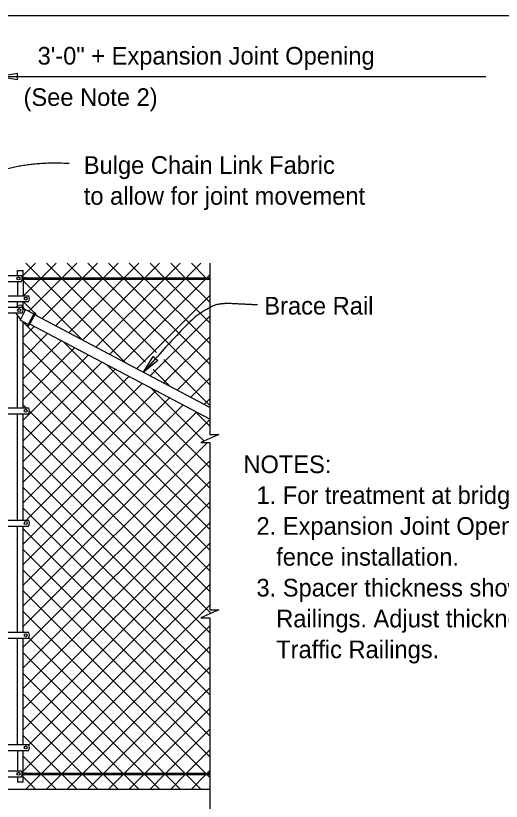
# Model space of a CAD drawing. Extents: x 0 to 72.1, y -7 to 30.
# Drawn here: x 28.78 to 34.31, y 19.05 to 28.01 of the extents above; entities that cross this region are included whole.
import ezdxf

# ---------------------------------------------------------------- set-up
doc = ezdxf.new("R2010")
doc.units = 0
for name, color, linetype in [('ActivePts-ConstElements', 7, 'Continuous'), ('AdhocPoint_dp', 7, 'Continuous'), ('Border', 7, 'Continuous'), ('PlotBorder_dp', 7, 'Continuous'), ('TextMisc', 7, 'Continuous'), ('TextStructures', 7, 'Continuous')]:
    doc.layers.add(name, color=color, linetype=linetype)

msp = doc.modelspace()

# ---------------------------------------------------------------- linework, layer by layer
at = {"layer": 'ActivePts-ConstElements'}
msp.add_lwpolyline([(0.016, 2.0538), (41.2266, 2.0538), (41.2266, 28.0138), (0.016, 28.0138)], close=True, dxfattribs=at)
at = {"layer": 'AdhocPoint_dp'}
for p, q in [((28.8631, 25.0498), (29.0033, 25.1899)), ((28.8958, 25.1899), (29.0625, 25.0233)), ((29.0723, 25.0233), (29.239, 25.1899)), ((29.1315, 25.1899), (29.2982, 25.0233)), ((29.308, 25.0233), (29.4747, 25.1899)), ((29.3672, 25.1899), (29.5339, 25.0233)), ((29.5437, 25.0233), (29.7104, 25.1899)), ((29.6029, 25.1899), (29.7696, 25.0233)), ((29.7794, 25.0233), (29.9461, 25.1899)), ((29.8386, 25.1899), (30.0053, 25.0233)), ((30.0151, 25.0233), (30.1818, 25.1899)), ((30.0743, 25.1899), (30.241, 25.0233)), ((30.2508, 25.0233), (30.4175, 25.1899)), ((30.31, 25.1899), (30.4767, 25.0233)), ((30.4865, 25.0233), (30.6532, 25.1899)), ((30.5457, 25.1899), (30.7124, 25.0233)), ((30.7222, 25.0233), (30.8889, 25.1899)), ((30.7814, 25.1899), (30.9481, 25.0233)), ((30.9579, 25.0233), (30.9922, 25.0576)), ((28.8631, 24.9869), (29.5355, 24.3145)), ((28.8682, 24.8192), (29.0575, 25.0085)), ((28.928, 24.6433), (29.2932, 25.0085)), ((29.0772, 25.0085), (30.0354, 24.0504)), ((29.0772, 24.5567), (29.5289, 25.0085)), ((29.2314, 24.4752), (29.7647, 25.0085)), ((29.3129, 25.0085), (30.2592, 24.0623)), ((29.3856, 24.3938), (30.0004, 25.0085)), ((29.5398, 24.3123), (30.2361, 25.0085)), ((29.5486, 25.0085), (30.3848, 24.1723)), ((29.694, 24.2308), (30.4718, 25.0085)), ((29.7843, 25.0085), (30.9922, 23.8006)), ((29.8482, 24.1493), (30.7075, 25.0085)), ((30.0024, 24.0678), (30.9432, 25.0085)), ((30.02, 25.0085), (30.9922, 24.0363)), ((30.2557, 25.0085), (30.9922, 24.2721)), ((30.4914, 25.0085), (30.9922, 24.5078)), ((30.7271, 25.0085), (30.9922, 24.7435)), ((28.8631, 24.7512), (28.992, 24.6224)), ((30.1566, 23.9863), (30.9922, 24.8219)), ((29.0019, 24.6125), (29.0357, 24.5787)), ((30.3108, 23.9048), (30.9922, 24.5862)), ((28.8631, 24.5155), (30.9922, 22.3864)), ((28.8631, 24.3427), (28.9884, 24.468)), ((28.8631, 24.107), (29.1426, 24.3865)), ((28.8631, 23.8713), (29.2968, 24.305)), ((30.4651, 23.8233), (30.9922, 24.3505)), ((28.8631, 24.2798), (30.9922, 22.1507)), ((28.8631, 23.6356), (29.451, 24.2235)), ((29.3234, 24.291), (30.9922, 22.6221)), ((28.8631, 23.3999), (29.6053, 24.142)), ((30.6193, 23.7418), (30.9922, 24.1148)), ((28.8631, 23.1642), (29.7595, 24.0605)), ((28.8631, 24.0441), (30.9922, 21.915)), ((29.8232, 24.0268), (30.9922, 22.8578)), ((30.4678, 24.0894), (30.9922, 23.5649)), ((28.8631, 22.9285), (29.9137, 23.979)), ((30.3442, 23.9773), (30.5352, 23.7862)), ((28.8631, 22.6928), (30.0679, 23.8975)), ((30.7735, 23.6603), (30.9922, 23.8791)), ((28.8631, 22.4571), (30.2221, 23.8161)), ((28.8631, 23.8084), (30.9922, 21.6793)), ((30.323, 23.7627), (30.9245, 23.1612)), ((28.9057, 22.264), (30.3763, 23.7346)), ((28.8631, 21.9857), (30.5305, 23.6531)), ((30.9277, 23.5788), (30.9922, 23.6434)), ((28.8631, 23.5727), (28.8972, 23.5386)), ((28.8631, 21.75), (30.6847, 23.5716)), ((28.8631, 21.5143), (30.8389, 23.4901)), ((28.9355, 23.5003), (30.9922, 21.4436)), ((30.8229, 23.4986), (30.9922, 23.3292)), ((28.8631, 21.2786), (30.9922, 23.4076)), ((28.8631, 23.337), (31.0051, 21.195)), ((28.8631, 21.0429), (30.966, 23.1457)), ((28.8631, 23.1013), (30.9922, 20.9722)), ((28.8631, 20.8072), (30.9922, 22.9362)), ((28.8631, 22.8656), (30.9922, 20.7365)), ((28.8631, 20.5715), (30.9922, 22.7005)), ((28.8631, 22.6299), (30.9922, 20.5008)), ((28.8631, 20.3358), (30.9922, 22.4648)), ((28.8631, 22.3942), (30.9922, 20.2651)), ((28.8631, 20.1001), (30.9922, 22.2291)), ((28.8631, 22.1585), (30.9922, 20.0294)), ((28.8631, 19.8644), (30.9922, 21.9934)), ((28.8631, 21.9228), (30.9922, 19.7937)), ((28.9289, 19.6944), (30.9922, 21.7577)), ((28.8631, 21.6871), (30.9922, 19.558)), ((28.8631, 19.393), (30.9922, 21.522)), ((28.8631, 21.4514), (30.9432, 19.3714)), ((29.0772, 19.3714), (30.9922, 21.2863)), ((28.8631, 21.2157), (30.7075, 19.3714)), ((29.3129, 19.3714), (30.9922, 21.0506)), ((28.9289, 20.9142), (30.4718, 19.3714)), ((29.5486, 19.3714), (30.9922, 20.8149)), ((28.8631, 20.7443), (30.2361, 19.3714)), ((29.7843, 19.3714), (30.9922, 20.5792)), ((28.8631, 20.5086), (30.0004, 19.3714)), ((28.8631, 20.2729), (29.7647, 19.3714)), ((30.02, 19.3714), (30.9922, 20.3435)), ((30.2557, 19.3714), (30.9922, 20.1078)), ((28.8631, 20.0372), (29.5289, 19.3714)), ((30.4914, 19.3714), (30.9922, 19.8721)), ((28.8631, 19.8015), (29.2932, 19.3714)), ((30.7271, 19.3714), (30.9922, 19.6364)), ((28.8631, 19.5658), (29.0575, 19.3714)), ((30.9628, 19.3714), (30.9922, 19.4007)), ((28.8631, 19.3301), (29.0033, 19.1899)), ((28.8958, 19.1899), (29.0625, 19.3566)), ((29.0723, 19.3566), (29.239, 19.1899)), ((29.1315, 19.1899), (29.2982, 19.3566)), ((29.308, 19.3566), (29.4747, 19.1899)), ((29.3672, 19.1899), (29.5339, 19.3566)), ((29.5437, 19.3566), (29.7104, 19.1899)), ((29.6029, 19.1899), (29.7696, 19.3566)), ((29.7794, 19.3566), (29.9461, 19.1899)), ((29.8386, 19.1899), (30.0053, 19.3566)), ((30.0151, 19.3566), (30.1818, 19.1899)), ((30.0743, 19.1899), (30.241, 19.3566)), ((30.2508, 19.3566), (30.4175, 19.1899)), ((30.31, 19.1899), (30.4767, 19.3566)), ((30.4865, 19.3566), (30.6532, 19.1899)), ((30.5457, 19.1899), (30.7124, 19.3566)), ((30.7222, 19.3566), (30.8889, 19.1899)), ((30.7814, 19.1899), (30.9481, 19.3566)), ((30.9579, 19.3566), (30.9922, 19.3223))]:
    msp.add_line(p, q, dxfattribs=at)
at = {"layer": 'Border'}
msp.add_line((25.6769, 27.321), (34.1393, 27.321), dxfattribs=at)
for points in [[(28.5923, 27.321), (28.8005, 27.2857), (28.8005, 27.3563)], [(30.3985, 24.0782), (30.2344, 23.9452), (30.3456, 24.1248)]]:
    msp.add_lwpolyline(points, close=True, dxfattribs=at)
for points in [[(30.9922, 25.192), (30.9922, 23.2357), (31.0955, 23.2357), (30.9922, 23.1907), (30.8889, 23.1457), (30.9922, 23.1457), (30.9922, 22.2521)], [(30.9922, 22.2521), (30.9922, 21.2344), (31.0955, 21.2344), (30.9922, 21.1894), (30.8889, 21.1444), (30.9922, 21.1444), (30.9922, 19.1899)], [(30.9922, 19.1899), (30.9922, 17.756), (31.0955, 17.756), (30.9922, 17.711), (30.8888, 17.666), (30.9922, 17.666), (30.9922, 15.3986)]]:
    msp.add_lwpolyline(points, dxfattribs=at)
for points in [[(29.3872, 26.3263), (28.9587, 26.3515), (28.2277, 26.1329), (27.9253, 25.5441), (27.7572, 24.0372)], [(31.5359, 24.7135), (31.3793, 24.7216), (31.0909, 24.7347), (30.9416, 24.6582), (30.734, 24.5124), (30.2344, 23.9452)]]:
    msp.add_open_spline(points, degree=2, dxfattribs=at)
at = {"layer": 'PlotBorder_dp'}
for p, q in [((28.8006, 25.0504), (28.8006, 25.1066)), ((28.8006, 25.1066), (28.8631, 25.1066)), ((28.8006, 25.0504), (28.8006, 25.1066)), ((28.8006, 25.1066), (28.8631, 25.1066)), ((28.8631, 25.0264), (28.8631, 25.1066)), ((28.8631, 25.0264), (28.8631, 25.1066)), ((28.4366, 25.0504), (28.8463, 25.0504)), ((28.8536, 25.0279), (28.8828, 25.0233)), ((28.8537, 25.0279), (28.8829, 25.0233)), ((28.8541, 25.0075), (28.8877, 25.0131)), ((28.8542, 25.0229), (28.8802, 25.0189)), ((28.8542, 25.0075), (28.8878, 25.0131)), ((28.8543, 25.0229), (28.8803, 25.0189)), ((28.8545, 25.0123), (28.8844, 25.0172)), ((28.8546, 25.0123), (28.8845, 25.0172)), ((28.8631, 25.0215), (28.8631, 25.0136)), ((28.8631, 25.0215), (28.8631, 25.0136)), ((28.9015, 25.0233), (30.9922, 25.0233)), ((28.4366, 24.9827), (28.846, 24.9827)), ((28.8006, 24.9826), (28.8006, 24.8191)), ((28.8006, 24.9826), (28.8006, 24.8191)), ((28.8631, 25.009), (28.8631, 24.8191)), ((28.8631, 25.009), (28.8631, 24.8191)), ((28.9002, 25.0085), (30.9922, 25.0085)), ((28.4366, 24.8192), (28.9276, 24.8192)), ((28.4366, 24.7516), (28.9269, 24.7516)), ((28.8006, 24.7025), (28.8006, 24.7516)), ((28.8631, 24.6949), (28.8631, 24.7516)), ((28.3299, 24.6896), (28.8547, 24.6896)), ((28.8923, 24.6621), (28.8286, 24.5416)), ((28.8888, 24.6556), (28.8541, 24.7087)), ((28.8923, 24.6621), (28.9866, 24.6123)), ((28.3299, 24.6218), (28.8547, 24.6218)), ((28.8328, 24.5496), (28.7859, 24.6213)), ((28.8006, 23.5386), (28.8006, 24.5988)), ((28.9912, 24.6209), (28.9187, 24.4838)), ((29.0031, 24.6147), (28.9306, 24.4776)), ((30.9922, 23.5447), (28.9953, 24.6)), ((28.9229, 24.4917), (28.8286, 24.5416)), ((28.8631, 23.5386), (28.8631, 24.5233)), ((30.9922, 23.4091), (28.9393, 24.494)), ((28.4366, 23.5386), (28.9276, 23.5386)), ((28.4366, 23.471), (28.9269, 23.471)), ((28.8006, 22.2581), (28.8006, 23.471)), ((28.8631, 22.2581), (28.8631, 23.471)), ((28.4366, 22.2581), (28.9276, 22.2581)), ((28.4366, 22.1905), (28.9269, 22.1905)), ((28.8006, 20.9776), (28.8006, 22.1905)), ((28.8631, 20.9776), (28.8631, 22.1905)), ((28.9276, 20.9776), (28.2577, 20.9776)), ((28.4366, 20.9101), (28.9269, 20.9101)), ((28.8006, 19.6971), (28.8006, 20.9099)), ((28.8631, 19.6971), (28.8631, 20.9099)), ((28.4366, 19.6972), (28.9276, 19.6972)), ((28.4366, 19.6295), (28.9269, 19.6295)), ((28.8006, 19.6295), (28.8006, 19.3985)), ((28.8631, 19.3745), (28.8631, 19.6295)), ((28.3385, 19.3985), (28.8463, 19.3985)), ((28.3385, 19.3985), (28.8463, 19.3985)), ((28.8536, 19.376), (28.8828, 19.3715)), ((28.8536, 19.376), (28.8828, 19.3715)), ((28.8537, 19.376), (28.8829, 19.3715)), ((28.8537, 19.376), (28.8829, 19.3715)), ((28.8542, 19.3709), (28.8802, 19.3669)), ((28.8542, 19.3709), (28.8802, 19.3669)), ((28.8543, 19.3709), (28.8803, 19.3669)), ((28.8543, 19.3709), (28.8803, 19.3669)), ((28.8545, 19.3603), (28.8844, 19.3653)), ((28.8545, 19.3603), (28.8844, 19.3653)), ((28.8546, 19.3603), (28.8845, 19.3653)), ((28.8546, 19.3603), (28.8845, 19.3653)), ((28.8631, 19.3617), (28.8631, 19.3695)), ((28.8631, 19.3617), (28.8631, 19.3695)), ((28.8631, 19.3617), (28.8631, 19.3695)), ((28.8631, 19.3617), (28.8631, 19.3695)), ((28.9015, 19.3714), (30.9922, 19.3714)), ((28.3387, 19.3307), (28.846, 19.3307)), ((28.3387, 19.3307), (28.846, 19.3307)), ((28.8006, 19.3307), (28.8006, 19.2733)), ((28.8006, 19.2733), (28.8631, 19.2733)), ((28.8541, 19.3556), (28.8877, 19.3613)), ((28.8541, 19.3556), (28.8877, 19.3613)), ((28.8542, 19.3556), (28.8878, 19.3613)), ((28.8542, 19.3556), (28.8878, 19.3613)), ((28.8631, 19.2733), (28.8631, 19.3571)), ((28.9002, 19.3566), (30.9922, 19.3566))]:
    msp.add_line(p, q, dxfattribs=at)
for centre, start, end in [((28.997, 24.6177), 332.14902, 152.14902), ((28.9245, 24.4805), 152.14902, 332.14902)]:
    msp.add_arc(centre, 0.00673, start, end, dxfattribs=at)
for centre, major_axis in [((28.8103, 25.0159), (-0.0178, 0)), ((28.8103, 25.0159), (-0.0178, 0)), ((28.8939, 24.7864), (-0.0177, 0)), ((28.8939, 24.7864), (-0.0177, 0)), ((28.8188, 24.655), (-0.0178, 0)), ((28.8939, 23.5059), (-0.0177, 0)), ((28.8939, 23.5059), (-0.0177, 0)), ((28.8939, 22.2254), (-0.0177, 0)), ((28.8939, 22.2254), (-0.0177, 0)), ((28.8939, 20.9449), (-0.0177, 0)), ((28.8939, 20.9449), (-0.0177, 0)), ((28.8939, 19.6644), (-0.0177, 0)), ((28.8103, 19.364), (-0.0178, 0)), ((28.8103, 19.364), (-0.0178, 0)), ((28.8103, 19.364), (-0.0178, 0)), ((28.8103, 19.364), (-0.0178, 0))]:
    msp.add_ellipse(centre, major_axis=major_axis, ratio=0.957868, dxfattribs=at)
for centre, major_axis, ratio, start_param, end_param in [((28.777, 25.0168), (0.0776, 0), 0.957868, 5.803915, 6.752041), ((28.777, 25.0168), (0.0776, 0), 0.957868, 5.803915, 6.752041), ((28.8854, 25.0135), (-0.0095, 0), 0.957868, 5.673972, 6.052579), ((28.8854, 25.0135), (-0.0095, 0), 0.957868, 5.673972, 6.052579), ((28.8854, 25.0135), (-0.0095, 0), 0.957868, 0.252467, 1.271421), ((28.8854, 25.0135), (-0.0095, 0), 0.957868, 0.252467, 1.271421), ((28.8795, 25.0093), (0.00982, 0), 0.957868, 0.655696, 1.505671), ((28.8795, 25.0093), (0.00982, 0), 0.957868, 0.655696, 1.505671), ((28.8814, 25.0142), (0.0115, -0.0041), 0.737732, 5.08821, 8.212701), ((28.8814, 25.0142), (0.0115, -0.0041), 0.737732, 5.08821, 8.212701), ((28.8848, 25.0117), (0.00301, 0), 0.957868, 3.28349, 5.170635), ((28.8848, 25.0117), (0.00301, 0), 0.957868, 3.28349, 5.170635), ((28.8855, 25.0139), (-0.00453, 0), 0.957868, 5.149727, 5.551998), ((28.8855, 25.0139), (-0.00453, 0), 0.957868, 5.149727, 5.551998), ((28.8827, 25.0126), (0.00527, 0), 0.957868, 5.058829, 7.342751), ((28.8827, 25.0126), (0.00527, 0), 0.957868, 5.058829, 7.342751), ((28.8871, 25.015), (-0.00872, 0), 0.957868, 2.1008, 4.992926), ((28.8871, 25.015), (-0.00872, 0), 0.957868, 2.1008, 4.992926), ((28.8848, 25.0117), (0.00301, 0), 0.957868, 0.004594, 0.141897), ((28.8848, 25.0117), (0.00301, 0), 0.957868, 0.004594, 0.141897), ((28.8932, 25.0146), (0.00944, 0), 0.957868, 4.316497, 6.557353), ((28.8932, 25.0146), (0.00944, 0), 0.957868, 4.316497, 6.557353), ((28.8936, 25.0155), (-0.00872, 0), 0.957868, 3.323334, 4.992926), ((28.8936, 25.0155), (-0.00872, 0), 0.957868, 3.323334, 4.992926), ((28.8936, 25.0155), (-0.00503, 0), 0.92697, 1.780895, 4.712389), ((28.8936, 25.0155), (-0.00503, 0), 0.92697, 1.780895, 4.712389), ((28.8984, 25.01), (-0.0142, 0), 0.957868, 3.141593, 4.79635), ((28.8984, 25.01), (-0.0142, 0), 0.957868, 3.141593, 4.79635), ((28.8904, 24.995), (0.0274, 0), 0.957868, 0.628521, 1.149654), ((28.8904, 24.995), (0.0274, 0), 0.957868, 0.628521, 1.149654), ((28.8581, 24.786), (0.0776, 0), 0.957868, 5.801244, 6.745158), ((28.8581, 24.786), (0.0776, 0), 0.957868, 5.801244, 6.745158), ((28.8375, 24.6404), (-0.0647, 0.0342), 0.957868, 4.95193, 6.011789), ((28.7855, 24.6554), (0.0776, 0), 0.957868, 5.810211, 6.75616), ((28.8581, 23.5055), (0.0776, 0), 0.957868, 5.801046, 6.744962), ((28.8581, 23.5055), (0.0776, 0), 0.957868, 5.801046, 6.744962), ((28.8581, 22.225), (0.0776, 0), 0.957868, 5.800848, 6.744767), ((28.8581, 22.225), (0.0776, 0), 0.957868, 5.800848, 6.744767), ((28.8581, 20.9446), (0.0776, 0), 0.957868, 5.800848, 6.744767), ((28.8581, 19.664), (0.0776, 0), 0.957868, 5.800651, 6.745353), ((28.777, 19.3649), (0.0776, 0), 0.957868, 5.803915, 6.752041), ((28.777, 19.3649), (0.0776, 0), 0.957868, 5.803915, 6.752041), ((28.777, 19.3649), (0.0776, 0), 0.957868, 5.803915, 6.752041), ((28.777, 19.3649), (0.0776, 0), 0.957868, 5.803915, 6.752041), ((28.8854, 19.3615), (-0.0095, 0), 0.957868, 5.673972, 6.052579), ((28.8854, 19.3615), (-0.0095, 0), 0.957868, 5.673972, 6.052579), ((28.8854, 19.3615), (-0.0095, 0), 0.957868, 5.673972, 6.052579), ((28.8854, 19.3615), (-0.0095, 0), 0.957868, 5.673972, 6.052579), ((28.8795, 19.3574), (0.00982, 0), 0.957868, 0.655696, 1.505671), ((28.8795, 19.3574), (0.00982, 0), 0.957868, 0.655696, 1.505671), ((28.8795, 19.3574), (0.00982, 0), 0.957868, 0.655696, 1.505671), ((28.8795, 19.3574), (0.00982, 0), 0.957868, 0.655696, 1.505671), ((28.8814, 19.3623), (0.0115, -0.0041), 0.737732, 5.08821, 8.212701), ((28.8814, 19.3623), (0.0115, -0.0041), 0.737732, 5.08821, 8.212701), ((28.8814, 19.3623), (0.0115, -0.0041), 0.737732, 5.08821, 8.212701), ((28.8814, 19.3623), (0.0115, -0.0041), 0.737732, 5.08821, 8.212701), ((28.8855, 19.362), (-0.00453, 0), 0.957868, 5.149727, 5.551998), ((28.8855, 19.362), (-0.00453, 0), 0.957868, 5.149727, 5.551998), ((28.8855, 19.362), (-0.00453, 0), 0.957868, 5.149727, 5.551998), ((28.8855, 19.362), (-0.00453, 0), 0.957868, 5.149727, 5.551998), ((28.8827, 19.3607), (0.00527, 0), 0.957868, 5.058829, 7.342751), ((28.8827, 19.3607), (0.00527, 0), 0.957868, 5.058829, 7.342751), ((28.8827, 19.3607), (0.00527, 0), 0.957868, 5.058829, 7.342751), ((28.8827, 19.3607), (0.00527, 0), 0.957868, 5.058829, 7.342751), ((28.8871, 19.3631), (-0.00872, 0), 0.957868, 2.1008, 4.992926), ((28.8871, 19.3631), (-0.00872, 0), 0.957868, 2.1008, 4.992926), ((28.8871, 19.3631), (-0.00872, 0), 0.957868, 2.1008, 4.992926), ((28.8871, 19.3631), (-0.00872, 0), 0.957868, 2.1008, 4.992926), ((28.8932, 19.3627), (0.00944, 0), 0.957868, 4.316497, 6.557353), ((28.8932, 19.3627), (0.00944, 0), 0.957868, 4.316497, 6.557353), ((28.8932, 19.3627), (0.00944, 0), 0.957868, 4.316497, 6.557353), ((28.8932, 19.3627), (0.00944, 0), 0.957868, 4.316497, 6.557353), ((28.8936, 19.3636), (-0.00872, 0), 0.957868, 3.323334, 4.992926), ((28.8936, 19.3636), (-0.00872, 0), 0.957868, 3.323334, 4.992926), ((28.8936, 19.3636), (-0.00872, 0), 0.957868, 3.323334, 4.992926), ((28.8936, 19.3636), (-0.00872, 0), 0.957868, 3.323334, 4.992926), ((28.8936, 19.3636), (-0.00503, 0), 0.92697, 1.780895, 4.712389), ((28.8936, 19.3636), (-0.00503, 0), 0.92697, 1.780895, 4.712389), ((28.8936, 19.3636), (-0.00503, 0), 0.92697, 1.780895, 4.712389), ((28.8936, 19.3636), (-0.00503, 0), 0.92697, 1.780895, 4.712389), ((28.8984, 19.3581), (-0.0142, 0), 0.957868, 3.141593, 4.79635), ((28.8984, 19.3581), (-0.0142, 0), 0.957868, 3.141593, 4.79635), ((28.8984, 19.3581), (-0.0142, 0), 0.957868, 3.141593, 4.79635), ((28.8984, 19.3581), (-0.0142, 0), 0.957868, 3.141593, 4.79635), ((28.8904, 19.3431), (0.0274, 0), 0.957868, 0.628521, 1.149654), ((28.8904, 19.3431), (0.0274, 0), 0.957868, 0.628521, 1.149654), ((28.8904, 19.3431), (0.0274, 0), 0.957868, 0.628521, 1.149654), ((28.8904, 19.3431), (0.0274, 0), 0.957868, 0.628521, 1.149654), ((28.8854, 19.3615), (-0.0095, 0), 0.957868, 0.252467, 1.271421), ((28.8854, 19.3615), (-0.0095, 0), 0.957868, 0.252467, 1.271421), ((28.8854, 19.3615), (-0.0095, 0), 0.957868, 0.252467, 1.271421), ((28.8854, 19.3615), (-0.0095, 0), 0.957868, 0.252467, 1.271421), ((28.8848, 19.3598), (0.00301, 0), 0.957868, 3.28349, 5.170635), ((28.8848, 19.3598), (0.00301, 0), 0.957868, 3.28349, 5.170635), ((28.8848, 19.3598), (0.00301, 0), 0.957868, 3.28349, 5.170635), ((28.8848, 19.3598), (0.00301, 0), 0.957868, 3.28349, 5.170635), ((28.8848, 19.3598), (0.00301, 0), 0.957868, 0.004594, 0.141897), ((28.8848, 19.3598), (0.00301, 0), 0.957868, 0.004594, 0.141897), ((28.8848, 19.3598), (0.00301, 0), 0.957868, 0.004594, 0.141897), ((28.8848, 19.3598), (0.00301, 0), 0.957868, 0.004594, 0.141897)]:
    msp.add_ellipse(centre, major_axis=major_axis, ratio=ratio, start_param=start_param, end_param=end_param, dxfattribs=at)
at = {"layer": 'TextMisc'}
msp.add_line((27.5923, 19.1899), (30.9922, 19.1899), dxfattribs=at)

# ---------------------------------------------------------------- texts
at = {"layer": 'Border'}
for s, p in [('Bulge Chain Link Fabric', (29.5553, 26.2091)), ('to allow for joint movement', (29.5553, 25.8571)), ('NOTES:', (31.3742, 22.7946)), ('  1. For treatment at bridge ends, see Sheet 1.', (31.3742, 22.4426)), ('  2. Expansion Joint Opening is the width at the time of', (31.3742, 22.0906)), ('     fence installation.', (31.3742, 21.7386)), ('  3. Spacer thickness shown is for Single-Slope Traffic', (31.3742, 21.3866)), ('     Railings. Adjust thickness as required for other', (31.3742, 21.0346)), ('     Traffic Railings.', (31.3742, 20.6826))]:
    msp.add_text(s, height=0.2016, dxfattribs=at).set_placement(p)
at = {"layer": 'TextStructures'}
for s, p in [('3\'-0" + Expansion Joint Opening', (29.0291, 27.4561)), ('(See Note 2)', (28.8684, 26.9844)), ('Brace Rail', (31.6132, 24.6036))]:
    msp.add_text(s, height=0.2016, dxfattribs=at).set_placement(p)

doc.saveas('drawing.dxf')
